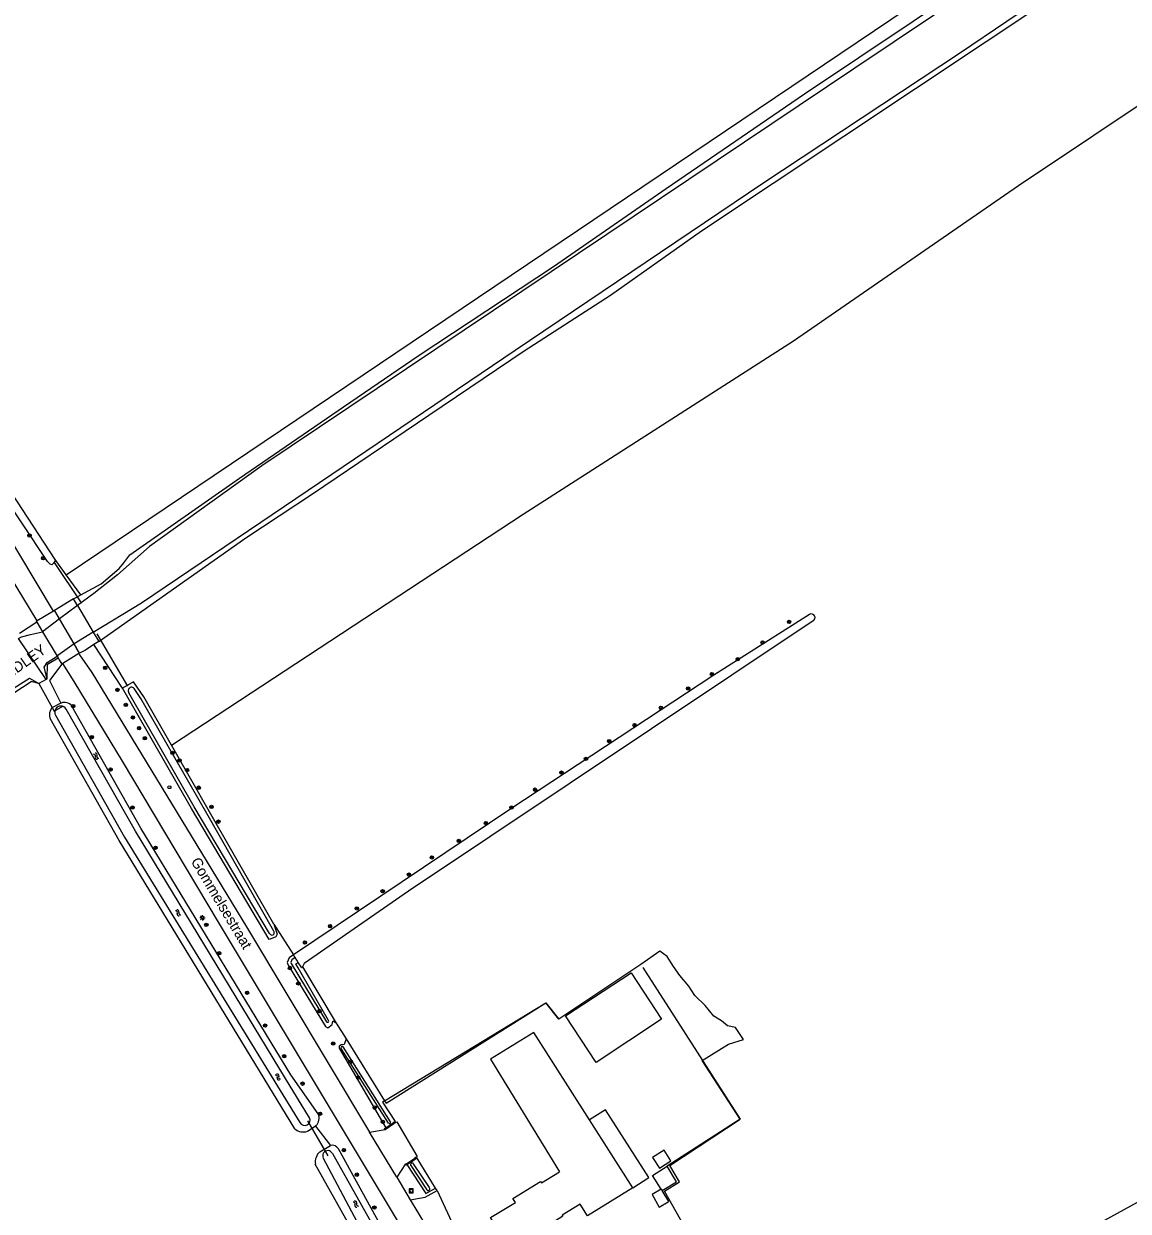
# Model space of a CAD drawing. Extents: x 137000 to 140001, y 403500 to 406000.
# Drawn here: x 138915.5 to 139177, y 404828.4 to 405109.4 of the extents above; entities that cross this region are included whole.
import ezdxf

# ---------------------------------------------------------------- set-up
doc = ezdxf.new("R2010")
doc.units = 0
for name, color, linetype in [('gg-afsc-erfafscheiding', 7, 'Continuous'), ('gg-afsc-hekwerk', 7, 'Continuous'), ('gg-anno-naam water', 7, 'Continuous'), ('gg-anno-openbare ruimte label', 7, 'Continuous'), ('gg-bbg-hoofdgebouw', 7, 'Continuous'), ('gg-bbg-luifel en loopbrug', 7, 'Continuous'), ('gg-bbg-overig bouwwerk', 7, 'Continuous'), ('gg-knt-bronhoudergrens', 7, 'Continuous'), ('gg-knt-onverhard', 7, 'Continuous'), ('gg-knt-verharding', 7, 'Continuous'), ('gg-knt-verharding nz', 7, 'Continuous'), ('gg-kntw-bovenkant insteek waterloop', 7, 'Continuous'), ('gg-kntw-greppel-droge sloot', 7, 'Continuous'), ('gg-kntw-waterlijn', 7, 'Continuous'), ('gg-kwrk-duiker nz buis', 7, 'Continuous'), ('gg-kwrk-kunstwerk niveau 01', 7, 'Continuous'), ('gt-grn-groengrens', 7, 'Continuous'), ('gt-grn-groengrens NZ', 7, 'Continuous'), ('gt-grn-vlakafsluiter', 7, 'Continuous'), ('gt-grn-weggrens', 7, 'Continuous'), ('gt-symb-boom', 7, 'Continuous'), ('gt-symb-brandkraan', 7, 'Continuous'), ('gt-symb-lichtmast', 7, 'Continuous'), ('gt-symb-rioolschacht', 7, 'Continuous'), ('gt-symb-watersymbool', 7, 'Continuous'), ('gx-grn-maaiveld', 7, 'Continuous')]:
    doc.layers.add(name, color=color, linetype=linetype)

# ---------------------------------------------------------------- blocks, each defined once
blk = doc.blocks.new('gt0-BOOM')
at = {"layer": 'gt-symb-boom'}
for radius in [0.4, 0.2]:
    blk.add_circle((0, 0), radius, dxfattribs=at)
blk = doc.blocks.new('gt0-BR')
at = {"layer": 'gt-symb-brandkraan'}
for centre, radius, start, end in [((-0.24, 0), 0.206, 107.5669, 252.4331), ((0.6, -2.66), 3, 106.892, 107.5669), ((0, -0.69), 0.938, 73.108, 106.892), ((-0.6, -2.66), 3, 72.4331, 73.108), ((0.24, 0), 0.206, 287.567, 72.4331), ((0.6, 2.66), 3, 252.4331, 253.108), ((0, 0.69), 0.938, 253.108, 286.8921), ((-0.6, 2.66), 3, 286.8921, 287.567)]:
    blk.add_arc(centre, radius, start, end, dxfattribs=at)
blk = doc.blocks.new('gt0-WA')
at = {"layer": 'gt-symb-watersymbool'}
for centre, start, end in [((-0.32, 0.02), 28.0725, 151.9275), ((0.43, 0.42), 208.0725, 331.9275), ((-0.32, -0.43), 28.0725, 151.9275), ((0.43, -0.03), 208.0725, 331.9275)]:
    blk.add_arc(centre, 0.425, start, end, dxfattribs=at)
blk = doc.blocks.new('gt0-LMAST')
at = {"layer": 'gt-symb-lichtmast'}
for p, q in [((-0.18, 0.17), (-0.45, 0.44)), ((-0.01, 0.25), (-0.01, 0.62)), ((0.17, 0.17), (0.44, 0.44)), ((-0.26, 0), (-0.63, 0)), ((-0.18, -0.18), (-0.45, -0.45)), ((-0.01, -0.25), (-0.01, -0.63)), ((0.44, -0.45), (0.17, -0.18)), ((0.24, 0), (0.62, 0))]:
    blk.add_line(p, q, dxfattribs=at)
blk.add_circle((-0.01, 0), 0.25, dxfattribs=at)
blk = doc.blocks.new('gt0-RS')
at = {"layer": 'gt-symb-rioolschacht'}
blk.add_lwpolyline([(-0.5, -0.5), (0.5, -0.5), (0.5, 0.5), (-0.5, 0.5)], close=True, dxfattribs=at)
blk.add_circle((0, 0), 0.375, dxfattribs=at)

msp = doc.modelspace()

# ---------------------------------------------------------------- linework, layer by layer
at = {"layer": 'gg-afsc-erfafscheiding'}
for p, q in [((139003, 404849.31), (139003.12, 404849.13)), ((139008.17, 404840.68), (139008.05, 404840.86)), ((139013.37, 404833.3), (139013.03, 404833.85))]:
    msp.add_line(p, q, dxfattribs=at)
at = {"layer": 'gg-afsc-hekwerk'}
for p, q in [((139062.05, 404886.04), (139085.09, 404850.14)), ((139000.93, 404854.51), (139039.08, 404877.74)), ((139039.08, 404877.74), (139042.16, 404873.81)), ((139085.09, 404850.14), (139067.84, 404839.05))]:
    msp.add_line(p, q, dxfattribs=at)
at = {"layer": 'gg-bbg-hoofdgebouw'}
msp.add_line((139059.68, 404833.96), (139049.46, 404849.98), dxfattribs=at)
for points in [[(139049.46, 404849.98), (139036.27, 404870.67), (139026, 404864.37), (139042.34, 404837.73)], [(139059.68, 404833.96), (139048.96, 404827.28), (139047.24, 404830.05), (139043, 404827.42), (139043.15, 404827.18), (139036.02, 404822.75), (139035.46, 404823.64), (139030.04, 404820.29), (139026.03, 404826.87), (139031.92, 404830.46), (139031.33, 404831.38), (139037.89, 404835.41), (139038.07, 404835.11), (139042.34, 404837.73)]]:
    msp.add_lwpolyline(points, dxfattribs=at)
at = {"layer": 'gg-bbg-luifel en loopbrug'}
for points in [[(139059.28, 404884.83), (139066.52, 404873.81), (139051.01, 404863.62), (139043.79, 404874.61), (139059.28, 404884.83)], [(139059.68, 404833.96), (139063.47, 404836.38), (139053.26, 404852.4), (139049.46, 404849.98)]]:
    msp.add_lwpolyline(points, dxfattribs=at)
at = {"layer": 'gg-bbg-overig bouwwerk'}
for p, q in [((139066.42, 404833.6), (139066.62, 404833.28)), ((139068.26, 404830.7), (139066.62, 404833.28)), ((139068.08, 404830.6), (139068.26, 404830.7))]:
    msp.add_line(p, q, dxfattribs=at)
for points in [[(139064.39, 404841.08), (139066.02, 404838.55), (139068.71, 404840.28), (139067.09, 404842.81), (139064.39, 404841.08)], [(139066.42, 404833.6), (139064.37, 404836.83), (139067.84, 404839.05)], [(139066.62, 404833.28), (139070.08, 404835.38), (139067.84, 404839.05)], [(139066.42, 404833.6), (139064.25, 404832.35), (139065.92, 404829.36), (139068.08, 404830.6)]]:
    msp.add_lwpolyline(points, dxfattribs=at)
at = {"layer": 'gg-knt-bronhoudergrens'}
for p, q in [((138925.6, 404978.99), (138922.97, 404982.63)), ((138974.74, 404896.3), (138979.35, 404889.09)), ((138989.5, 404872.93), (138991.84, 404869.2)), ((138984.6, 404848.54), (138988.15, 404843.98))]:
    msp.add_line(p, q, dxfattribs=at)
for points in [[(139037.66, 404792.46), (139075.83, 404817.93), (139067.22, 404833.1), (139070.72, 404835.33), (139068.44, 404839.22), (139085.09, 404850.14), (139076.16, 404864.06), (139082.38, 404867.96), (139085.94, 404869.01), (139084.03, 404871.84), (139082.12, 404872.23), (139080.67, 404873.42), (139078.9, 404874.54), (139076.86, 404877.04), (139074.36, 404879.47), (139072.98, 404881.64), (139070.8, 404884.14), (139069.36, 404886.31), (139067.84, 404888.68), (139066.07, 404889.93), (139061.58, 404886.77), (139042.16, 404873.81)], [(139122.5, 404790.77), (139118.46, 404797.17), (139179.18, 404830.53), (139224.62, 404855.9), (139280.61, 404887.21)], [(139000.93, 404854.51), (139001.29, 404853.93), (139039.08, 404877.74)]]:
    msp.add_lwpolyline(points, dxfattribs=at)
at = {"layer": 'gg-knt-onverhard'}
msp.add_line((139042.16, 404873.81), (139039.08, 404877.74), dxfattribs=at)
msp.add_lwpolyline([(138922.97, 404982.63), (138911.37, 405000.4), (138893.55, 405028.77)], dxfattribs=at)
at = {"layer": 'gg-knt-verharding'}
for p, q in [((139001.05, 404847.77), (139003.12, 404849.13)), ((139005.97, 404839.53), (139008.05, 404840.86)), ((139003.83, 404836.43), (139007.02, 404831.11)), ((139013.37, 404833.3), (139017.74, 404823.94))]:
    msp.add_line(p, q, dxfattribs=at)
for points in [[(138922.61, 404970.39), (138910.3, 404991.03), (138891.21, 405021.46), (138885.83, 405029.64)], [(138918.73, 404968.08), (138906.67, 404987.94), (138887.3, 405018.74), (138881.81, 405027.07)], [(138928.58, 404960.38), (138928.75, 404960.09), (138931.66, 404955.92), (138968.25, 404895.7), (138997.4, 404847.13)], [(139066.78, 404721.54), (138961.66, 404896.8), (138938.92, 404934.88), (138927.44, 404953.75), (138924.75, 404958.01)], [(138997.4, 404847.13), (139001.09, 404847.71), (139001.05, 404847.77)], [(139003.12, 404849.13), (139003.85, 404849.52), (139008.67, 404841.36), (139008.05, 404840.86)], [(139005.97, 404839.53), (139005.93, 404839.6), (139003.83, 404836.43)], [(139007.02, 404831.11), (139010.54, 404831.69), (139013.37, 404833.3)]]:
    msp.add_lwpolyline(points, dxfattribs=at)
at = {"layer": 'gg-knt-verharding nz'}
for p, q in [((139003.83, 404836.43), (138997.4, 404847.13)), ((139007.02, 404831.11), (139014.07, 404819.36))]:
    msp.add_line(p, q, dxfattribs=at)
at = {"layer": 'gg-kntw-bovenkant insteek waterloop'}
for p, q in [((138927.31, 404973.3), (138922.83, 404970.53)), ((138918.61, 404967.81), (138914.56, 404965.16)), ((138933.27, 404963.26), (138932.15, 404962.52)), ((138902.3, 404943.97), (138917.28, 404953.74)), ((138919.1, 404953.29), (138917.28, 404953.74)), ((138920.85, 404954.27), (138919.1, 404953.29)), ((138921.04, 404954.37), (138920.85, 404954.27)), ((138924.32, 404948.65), (138922.21, 404947.51)), ((138924.36, 404948.67), (138924.32, 404948.65)), ((138981.49, 404886.23), (138989.5, 404872.93)), ((138989.5, 404872.93), (138988.73, 404873.37)), ((138991.84, 404869.2), (139000.93, 404854.51)), ((139000.93, 404854.51), (139000.42, 404854.19)), ((138984.71, 404848.64), (138984.6, 404848.54)), ((139001.27, 404848.16), (139003, 404849.31)), ((138985.65, 404842.48), (138988.15, 404843.98)), ((139005.62, 404814.86), (138990.01, 404843.14)), ((138999.75, 404812.46), (138984.55, 404839.53)), ((139006.2, 404839.41), (139008.17, 404840.68)), ((139006.2, 404839.41), (139010.72, 404832.55)), ((139010.72, 404832.55), (139013.03, 404833.85))]:
    msp.add_line(p, q, dxfattribs=at)
for points in [[(138929.02, 404974.27), (138933.82, 404976.89), (138938.1, 404980.47), (138939.19, 404981.83), (138940.64, 404983.75), (138966.62, 405001.9), (138991.22, 405018.78), (139009.17, 405031.01), (139040.96, 405052.01), (139067.57, 405070.45), (139100.33, 405092.85), (139138.9, 405118.72), (139167.16, 405137.78)], [(138933.27, 404963.26), (138968.09, 404987.78), (138983.86, 404998.15), (139011.4, 405016.8), (139034.02, 405032.02), (139054.44, 405045.22), (139075.96, 405060.43), (139160.31, 405116.58), (139174.66, 405126.44)], [(138927.31, 404973.3), (138927.78, 404973.59), (138929.02, 404974.27)], [(139101.55, 404969.65), (139078.92, 404955.24), (139030.83, 404923.62), (138979.35, 404889.09)], [(139102.4, 404968.09), (139006.62, 404904.13), (138981.91, 404887.01), (138981.49, 404886.23)], [(138932.15, 404962.52), (138930.17, 404961.2), (138928.75, 404960.48)], [(138921.04, 404954.37), (138921.16, 404957.83), (138923.68, 404959.33)], [(138950.52, 404938.66), (138943.94, 404950.15), (138941.51, 404953.68), (138938.9, 404952.18)], [(138974.74, 404896.3), (138975.48, 404893.93), (138975.18, 404893.36), (138974.29, 404892.93), (138973.6, 404892.7), (138955.21, 404923.67), (138938.9, 404952.18)], [(138973.7, 404894.09), (138955.9, 404924.08), (138940.44, 404951.1)], [(138974.74, 404894.69), (138958.84, 404922.53), (138949.83, 404938.26), (138943.26, 404949.72), (138941.64, 404952.08)], [(138985.26, 404851.4), (138978.74, 404860.63), (138943.24, 404919.08), (138926.9, 404947.96)], [(138979.73, 404847.87), (138938.08, 404916.14), (138921.75, 404945.03)], [(138974.74, 404896.3), (138959.54, 404922.93), (138950.52, 404938.66)], [(138979.35, 404889.09), (138978.34, 404888.39), (138977.89, 404887.24), (138978.14, 404886.64), (138986.98, 404872.09), (138987.5, 404871.81), (138988.57, 404872.58), (138988.73, 404873.37)], [(138991.37, 404867.88), (138990.68, 404867.8), (138990.2, 404867.42), (138990.23, 404866.99), (139001.27, 404848.16)], [(139000.42, 404854.19), (139003.45, 404849.6), (139003, 404849.31)], [(138984.6, 404848.54), (138982.83, 404847.37), (138982.72, 404847.33)], [(139013.03, 404833.85), (139008.62, 404840.97), (139008.17, 404840.68)]]:
    msp.add_lwpolyline(points, dxfattribs=at)
for centre, radius, start, end in [((139101.97, 404968.87), 0.89, 298.8703, 118.4945), ((138941.02, 404951.62), 0.773, 37.0488, 221.8119), ((138925.14, 404946.56), 2.25, 38.5979, 110.2817), ((138924.34, 404945.83), 2.72, 141.8653, 197.0938), ((138974.24, 404894.35), 0.603, 205.2121, 34.9989), ((138982.94, 404850.42), 2.51, 314.7217, 22.7943), ((138981.68, 404850.11), 2.97, 228.9069, 290.534), ((138987.81, 404840), 3.29, 131.0867, 188.3074), ((138988.51, 404842.31), 1.71, 28.9359, 102.1436)]:
    msp.add_arc(centre, radius, start, end, dxfattribs=at)
at = {"layer": 'gg-kntw-greppel-droge sloot'}
msp.add_lwpolyline([(138922.97, 404982.63), (138922.9, 404982.23), (138922.61, 404981.73), (138922.21, 404981.4), (138921.75, 404981.53), (138921.12, 404982.16), (138908.89, 405000.49), (138900.18, 405014.48), (138891.5, 405028.17), (138891.37, 405028.57), (138891.76, 405028.96), (138892.26, 405029.26), (138893.18, 405029.07), (138893.55, 405028.77)], dxfattribs=at)
at = {"layer": 'gg-kntw-waterlijn'}
for p, q in [((138928.25, 404971.72), (138923.98, 404968.59)), ((138923.98, 404968.59), (138919.96, 404965.55)), ((138931.99, 404965.41), (138927.48, 404962.65)), ((138979.78, 404888.42), (138979.35, 404889.09)), ((138981.36, 404885.97), (138980.51, 404887.29)), ((138981.49, 404886.23), (138981.36, 404885.97)), ((139001.84, 404849.25), (138990.66, 404866.94)), ((139002.35, 404849.57), (138991.16, 404867.26)), ((138988.59, 404842.07), (139004.27, 404814.17)), ((138986.43, 404840.98), (139001.39, 404812.71)), ((139007.12, 404839.18), (139010.94, 404833.44)), ((139011.55, 404833.97), (139007.79, 404839.62))]:
    msp.add_line(p, q, dxfattribs=at)
for points in [[(139168.11, 405136.36), (139112.24, 405098.91), (139040.37, 405050.72), (138971.9, 405004.81), (138945.32, 404985.68), (138937.73, 404978.98), (138932.13, 404974.57), (138928.25, 404971.72)], [(138931.99, 404965.41), (138943.37, 404972.38), (138988.49, 405002.84), (139031.89, 405032.14), (139090.49, 405071.69), (139137.29, 405102.59), (139170.15, 405124.92), (139173.97, 405127.5)], [(138914.3, 404963.97), (138914.96, 404964.32), (138917.13, 404964.92), (138919.96, 404965.55)], [(138927.48, 404962.65), (138923.62, 404959.89), (138923.45, 404959.73)], [(138921.04, 404954.37), (138920.37, 404957.14), (138921.1, 404958.26), (138923.45, 404959.73)], [(138550.87, 404716.47), (138551.76, 404716.74), (138552.07, 404716.83), (138553.89, 404718.16), (138605.37, 404739.64), (138628.59, 404749.55), (138655.52, 404762.21), (138659.67, 404764.36), (138683.07, 404776.96), (138697.75, 404785.54), (138723.47, 404802.58), (138740.24, 404815), (138752.18, 404824.25), (138758.91, 404829.66), (138782.69, 404850.62), (138802.79, 404869.24), (138832.84, 404895.64), (138842.15, 404903.29), (138846.79, 404906.78), (138853.84, 404912.35), (138867.96, 404922.01), (138893.08, 404939.54), (138916.88, 404954.53), (138919.1, 404953.29)], [(138923.05, 404945.77), (138939.38, 404916.9), (138980.91, 404849.41)], [(138983.21, 404850.53), (138977.48, 404859.8), (138941.95, 404918.32), (138925.6, 404947.22)], [(138979.78, 404888.42), (138979, 404887.87), (138978.75, 404887.25), (138978.85, 404887), (138987.2, 404873.25)], [(138987.69, 404873.54), (138981.43, 404884.31), (138980.47, 404886.01), (138979.93, 404886.97), (138980.51, 404887.29)]]:
    msp.add_lwpolyline(points, dxfattribs=at)
for centre, radius, start, end in [((138924.32, 404946.5), 1.46, 29.7546, 209.7837), ((138987.46, 404873.38), 0.282, 206.7671, 34.6707), ((138990.91, 404867.11), 0.3, 31.5017, 213.0156), ((138982.06, 404849.97), 1.28, 205.9421, 25.9055), ((139002.09, 404849.42), 0.3, 213.1757, 31.5031), ((138987.51, 404841.52), 1.21, 26.6922, 206.7343), ((139007.46, 404839.4), 0.4, 33.7299, 213.5311), ((139011.27, 404833.68), 0.404, 217.1069, 44.142)]:
    msp.add_arc(centre, radius, start, end, dxfattribs=at)
at = {"layer": 'gg-kwrk-duiker nz buis'}
for p, q in [((138922.72, 404981.91), (138929.12, 404972.39)), ((138940.19, 404952.68), (138932.9, 404965.05)), ((138982.7, 404849.77), (138987.55, 404841.48))]:
    msp.add_line(p, q, dxfattribs=at)
msp.add_lwpolyline([(138919.1, 404953.29), (138922.71, 404946.75), (138924.79, 404947.94)], dxfattribs=at)
at = {"layer": 'gg-kwrk-kunstwerk niveau 01'}
for p, q in [((138918.61, 404967.81), (138919.96, 404965.55)), ((138922.61, 404970.39), (138918.73, 404968.08)), ((138922.83, 404970.53), (138922.61, 404970.39)), ((138927.48, 404962.65), (138923.98, 404968.59)), ((138919.96, 404965.55), (138923.45, 404959.73)), ((138923.45, 404959.73), (138923.68, 404959.33)), ((138928.58, 404960.38), (138924.75, 404958.01)), ((138928.58, 404960.38), (138928.75, 404960.48)), ((138924.75, 404958.01), (138924.55, 404957.88))]:
    msp.add_line(p, q, dxfattribs=at)
for points in [[(138918.61, 404967.81), (138918.52, 404967.96), (138918.73, 404968.08)], [(138923.98, 404968.59), (138923.11, 404970.07), (138922.83, 404970.53)], [(138928.75, 404960.48), (138928.05, 404961.68), (138928.04, 404961.69), (138927.48, 404962.65)], [(138923.68, 404959.33), (138923.93, 404958.92), (138924.55, 404957.88)]]:
    msp.add_lwpolyline(points, dxfattribs=at)
at = {"layer": 'gt-grn-groengrens'}
msp.add_line((138925.6, 404978.99), (139166.02, 405140.98), dxfattribs=at)
msp.add_lwpolyline([(138950.52, 404938.66), (139033.78, 404993.36), (139097.72, 405034.38), (139151.01, 405071.17), (139186.41, 405094.79), (139191.14, 405097.85)], dxfattribs=at)
at = {"layer": 'gt-grn-groengrens NZ'}
for p, q in [((138929.02, 404974.27), (138925.6, 404978.99)), ((138938.9, 404952.18), (138932.15, 404962.52))]:
    msp.add_line(p, q, dxfattribs=at)
msp.add_lwpolyline([(138924.55, 404957.88), (138921.65, 404953.98), (138924.32, 404948.65)], dxfattribs=at)
at = {"layer": 'gt-grn-vlakafsluiter'}
for p, q in [((138928.25, 404971.72), (138927.31, 404973.3)), ((138928.25, 404971.72), (138931.99, 404965.41)), ((138931.99, 404965.41), (138933.27, 404963.26)), ((138920.85, 404954.27), (138914.3, 404963.97))]:
    msp.add_line(p, q, dxfattribs=at)
msp.add_lwpolyline([(138980.51, 404887.29), (138980.16, 404887.83), (138979.78, 404888.42)], dxfattribs=at)
at = {"layer": 'gt-grn-weggrens'}
for points in [[(139001.05, 404847.77), (139000.94, 404847.94), (139001.27, 404848.16)], [(139005.97, 404839.53), (139006.09, 404839.34), (139006.2, 404839.41)]]:
    msp.add_lwpolyline(points, dxfattribs=at)
at = {"layer": 'gx-grn-maaiveld'}
msp.add_line((138991.84, 404869.2), (138991.37, 404867.88), dxfattribs=at)

# ---------------------------------------------------------------- block references
at = {"layer": 'gt-symb-boom'}
for p in [(138916.89, 404988.32), (138920.1, 404982.95), (139096.7, 404967.85), (139090.44, 404962.99), (139084.54, 404959.02), (138934.81, 404956.99), (139078.42, 404955.51), (138937.71, 404951.78), (139072.81, 404952.11), (138927.26, 404947.95), (138939.69, 404948.21), (138941.36, 404945.26), (139066.37, 404947.53), (138942.84, 404942.72), (139060.13, 404943.43), (138931.65, 404940.6), (138944.2, 404940.33), (139054.11, 404939.65), (138950.74, 404936.87), (138952.4, 404935.09), (139048.62, 404935.43), (138936.1, 404932.93), (138954.2, 404932.8), (139042.79, 404932.19), (138956.95, 404928.63), (139036.58, 404928.16), (138941.28, 404923.93), (138959.98, 404924.07), (139030.99, 404923.92), (138961.6, 404920.59), (139024.92, 404920.24), (138946.75, 404914.42), (139018.51, 404916.04), (139012.14, 404912.14), (139006.71, 404908.06), (139000.49, 404904.12), (138994.37, 404900.06), (138958.75, 404896.14), (138988.05, 404895.85), (138982.08, 404891.99), (138961.8, 404889.44), (138978.54, 404885.95), (138980.53, 404882.31), (138968.39, 404880.1), (138985.52, 404875.77), (138972.65, 404872.32), (138988.77, 404868.06), (138977.2, 404865.07), (138992.95, 404863.78), (138981.53, 404858.58), (138994.66, 404860.03), (138998.63, 404852.9), (138985.69, 404851.46), (139000.5, 404849.57), (138991.33, 404842.85), (138994.38, 404837.04), (138998.52, 404829.24)]:
    msp.add_blockref('gt0-BOOM', p, dxfattribs=at)
at = {"layer": 'gt-symb-brandkraan'}
msp.add_blockref('gt0-BR', (138950.01, 404928.74), dxfattribs=at)
at = {"layer": 'gt-symb-lichtmast'}
msp.add_blockref('gt0-LMAST', (138957.83, 404897.82), dxfattribs=at)
at = {"layer": 'gt-symb-rioolschacht'}
msp.add_blockref('gt0-RS', (139007.25, 404833.22), dxfattribs=at)
at = {"layer": 'gt-symb-watersymbool'}
for p, rotation in [((138932.71, 404936.03), 126.9958977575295), ((138952.09, 404898.96), 126.9958977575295), ((138975.74, 404860.11), 126.9958977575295), ((138994.15, 404830.04), 126.99589775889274)]:
    msp.add_blockref('gt0-WA', p, dxfattribs=dict(at, rotation=rotation))

# ---------------------------------------------------------------- texts
at = {"layer": 'gg-anno-naam water'}
msp.add_text('ZANDLEY', height=2.5, rotation=34.9451, dxfattribs=at).set_placement((138908.44, 404951.81))
at = {"layer": 'gg-anno-openbare ruimte label'}
msp.add_text('Gommelsestraat', height=2.5, rotation=300.9, dxfattribs=at).set_placement((138954.99, 404911.19))

doc.saveas('drawing.dxf')
